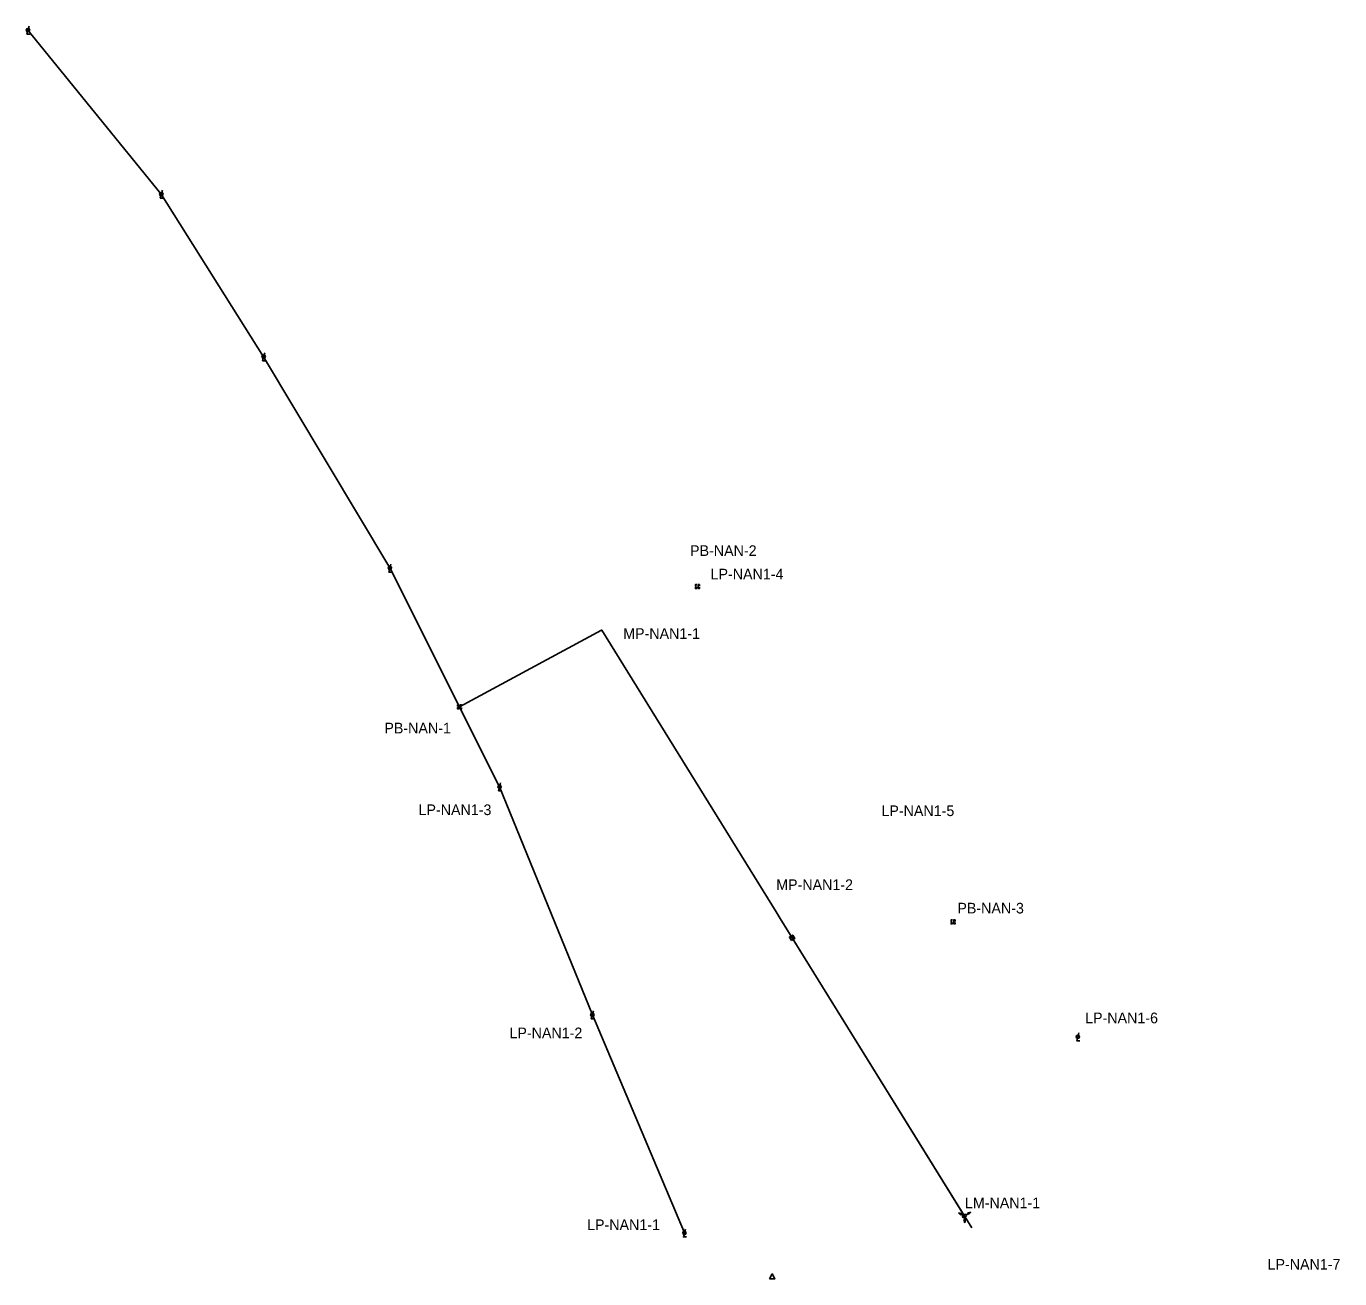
# Model space of a CAD drawing. Extents: x 1689971 to 1704302, y 703122 to 745602.
# Drawn here: x 1696774 to 1697760, y 719352 to 720292 of the extents above; entities that cross this region are included whole.
import ezdxf

# ---------------------------------------------------------------- set-up
doc = ezdxf.new("R2010")
doc.units = 0
for name, color, linetype in [('_CIVIL_CONSTRUCTION', 7, 'Continuous'), ('GK_Drainage_Nodes', 7, 'Continuous'), ('RD_X_Cells', 7, 'Continuous'), ('RD_X_Concrete_Barrier', 7, 'Continuous'), ('SC_Scratch3', 7, 'Continuous'), ('SC_Scratch4', 7, 'Continuous'), ('SV_X_Control_Cells_Found', 7, 'Continuous'), ('SV_X_Random_Point', 7, 'Continuous'), ('SV_X_Shot_Marker', 7, 'Continuous')]:
    doc.layers.add(name, color=color, linetype=linetype)

msp = doc.modelspace()

# ---------------------------------------------------------------- linework, layer by layer
at = {"layer": '_CIVIL_CONSTRUCTION'}
for p, q in [((1696875.8, 720166.16), (1696775.73, 720289.15)), ((1696952.6, 720044.16), (1696875.8, 720166.16)), ((1697047.4, 719885.6), (1696952.6, 720044.16)), ((1697129.73, 719721.48), (1697047.4, 719885.61)), ((1697199.37, 719550.35), (1697129.73, 719721.48)), ((1697268.47, 719386.61), (1697199.37, 719550.35))]:
    msp.add_line(p, q, dxfattribs=at)
for points in [[(1697206.29, 719839.04), (1697206.29, 719839.04), (1697099.67, 719781.4)], [(1697340.39, 719622.56), (1697337.3, 719627.54), (1697206.38, 719838.9)]]:
    msp.add_lwpolyline(points, dxfattribs=at)
at = {"layer": 'GK_Drainage_Nodes'}
msp.add_lwpolyline([(1697332.45, 719352.25), (1697336.45, 719352.25), (1697334.45, 719355.84), (1697332.45, 719352.25)], dxfattribs=at)
at = {"layer": 'RD_X_Cells'}
for p, q in [((1697349.34, 719608.11), (1697340.39, 719622.56)), ((1697478.69, 719399.3), (1697349.34, 719608.11))]:
    msp.add_line(p, q, dxfattribs=at)
at = {"layer": 'RD_X_Concrete_Barrier'}
msp.add_line((1697484.15, 719390.48), (1697340.39, 719622.56), dxfattribs=at)
at = {"layer": 'SC_Scratch3'}
for points in [[(1696776.52, 720292.1), (1696774.95, 720286.12), (1696777.31, 720286.12)], [(1696876.59, 720169.12), (1696875.01, 720163.13), (1696877.38, 720163.13)], [(1696953.39, 720047.15), (1696951.81, 720041.16), (1696954.18, 720041.16)], [(1697048.18, 719888.57), (1697046.61, 719882.58), (1697048.97, 719882.58)], [(1697130.51, 719724.43), (1697128.94, 719718.45), (1697131.3, 719718.45)], [(1697200.16, 719553.31), (1697198.58, 719547.32), (1697200.95, 719547.32)], [(1697564.53, 719536.76), (1697562.95, 719530.77), (1697565.32, 719530.77)], [(1697269.26, 719389.56), (1697267.68, 719383.58), (1697270.05, 719383.58)]]:
    msp.add_lwpolyline(points, dxfattribs=at)
for centre in [(1696775.73, 720289.15), (1696875.8, 720166.16), (1696952.6, 720044.19), (1697047.4, 719885.61), (1697129.73, 719721.48), (1697199.37, 719550.35), (1697563.74, 719533.8), (1697268.47, 719386.61)]:
    msp.add_circle(centre, 1.3, dxfattribs=at)
at = {"layer": 'SC_Scratch4'}
for p, q in [((1697278.24, 719871.63), (1697278.24, 719871.63)), ((1697099.67, 719781.4), (1697099.67, 719781.4)), ((1697470.14, 719620.01), (1697470.14, 719620.01))]:
    msp.add_line(p, q, dxfattribs=at)
for points in [[(1697277.84, 719873.13), (1697276.74, 719873.13), (1697276.74, 719872.03)], [(1697276.74, 719871.23), (1697276.74, 719870.13), (1697277.84, 719870.13)], [(1697277.15, 719872.63), (1697277.15, 719870.63), (1697278.24, 719870.63)], [(1697278.2, 719872.63), (1697279.44, 719872.63)], [(1697279.74, 719872.03), (1697279.74, 719873.13), (1697278.64, 719873.13)], [(1697278.64, 719870.13), (1697279.74, 719870.13), (1697279.74, 719871.23)], [(1697278.83, 719872.63), (1697278.83, 719870.63)], [(1697099.27, 719782.9), (1697098.17, 719782.9), (1697098.17, 719781.8)], [(1697098.17, 719781), (1697098.17, 719779.9), (1697099.27, 719779.9)], [(1697098.58, 719782.4), (1697098.58, 719780.4), (1697099.67, 719780.4)], [(1697099.62, 719782.4), (1697100.87, 719782.4)], [(1697101.17, 719781.8), (1697101.17, 719782.9), (1697100.07, 719782.9)], [(1697100.07, 719779.9), (1697101.17, 719779.9), (1697101.17, 719781)], [(1697100.25, 719782.4), (1697100.25, 719780.4)], [(1697469.74, 719621.51), (1697468.64, 719621.51), (1697468.64, 719620.41)], [(1697468.64, 719619.61), (1697468.64, 719618.51), (1697469.74, 719618.51)], [(1697469.05, 719621.01), (1697469.05, 719619.01), (1697470.14, 719619.01)], [(1697470.1, 719621.01), (1697471.34, 719621.01)], [(1697471.64, 719620.41), (1697471.64, 719621.51), (1697470.54, 719621.51)], [(1697470.54, 719618.51), (1697471.64, 719618.51), (1697471.64, 719619.61)], [(1697470.72, 719621.01), (1697470.72, 719619.01)]]:
    msp.add_lwpolyline(points, dxfattribs=at)
at = {"layer": 'SV_X_Control_Cells_Found'}
for p, q in [((1697476.63, 719401.13), (1697474.21, 719401.7)), ((1697474.21, 719401.7), (1697476.02, 719400)), ((1697480.05, 719400.14), (1697481.58, 719401.09)), ((1697483.45, 719402.25), (1697481.07, 719401.53)), ((1697481.75, 719400.43), (1697483.45, 719402.25)), ((1697477.73, 719399.81), (1697476.15, 719400.66)), ((1697478.13, 719396.59), (1697478.85, 719394.21)), ((1697478.73, 719398.21), (1697478.78, 719396.41)), ((1697478.85, 719394.21), (1697479.42, 719396.63))]:
    msp.add_line(p, q, dxfattribs=at)
for centre, start, end in [((1697477.15, 719400.12), 117.2518, 186.32967), ((1697480.62, 719400.49), 357.2518, 66.32967), ((1697478.75, 719397.55), 237.2518, 306.32967)]:
    msp.add_arc(centre, 1.13, start, end, dxfattribs=at)
msp.add_ellipse((1697478.69, 719399.3), major_axis=(1.36, 0.84), ratio=0.625, dxfattribs=at)
at = {"layer": 'SV_X_Shot_Marker'}
msp.add_line((1697349.34, 719608.11), (1697349.34, 719608.11), dxfattribs=at)
msp.add_lwpolyline([(1697348.85, 719606.05), (1697347.28, 719608.6), (1697349.84, 719610.17), (1697351.4, 719607.61)], close=True, dxfattribs=at)
for points in [[(1697348.51, 719607.55), (1697347.86, 719608.61)], [(1697348.18, 719608.08), (1697349.89, 719609.13)], [(1697349.06, 719606.66), (1697350.76, 719607.71), (1697350.19, 719608.63)]]:
    msp.add_lwpolyline(points, dxfattribs=at)

# ---------------------------------------------------------------- texts
at = {"layer": 'SV_X_Random_Point'}
for s, p in [('PB-NAN-2', (1697272.7, 719894.62)), ('LP-NAN1-4', (1697288.1, 719877.02)), ('MP-NAN1-1', (1697222.51, 719832.41)), ('PB-NAN-1', (1697043.24, 719761.48)), ('LP-NAN1-3', (1697068.89, 719700.16)), ('LP-NAN1-5', (1697416.36, 719699.43)), ('MP-NAN1-2', (1697337.37, 719643.94)), ('PB-NAN-3', (1697473.36, 719626.33)), ('LP-NAN1-6', (1697569.26, 719543.96)), ('LP-NAN1-2', (1697137.15, 719532.72)), ('LM-NAN1-1', (1697479.05, 719405.16)), ('LP-NAN1-1', (1697195.41, 719388.77)), ('LP-NAN1-7', (1697706.22, 719359.06))]:
    msp.add_text(s, height=8, dxfattribs=at).set_placement(p)

doc.saveas('drawing.dxf')
